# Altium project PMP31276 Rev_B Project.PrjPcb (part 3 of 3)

## Sheet PMP31276 Rev_B LaunchPad Schematic.SchDoc: LaunchPad / Aux supply
size 431 x 279 mm; Date: Not shown in title block; ApprovedBy: Not shown in title block; CheckedBy: Not shown in title block; Author: Not shown in title block; CompanyName: Not shown in title block; DrawnBy: R. Scibilia; Engineer: Not shown in title block; Organization: Not shown in title block; Address1: Not shown in title block; Address2: Not shown in title block; Address3: Not shown in title block; Address4: Not shown in title block; DocumentNumber: 1; Revision: Use project parameter SCH_Rev; SheetNumber: 4; SheetTotal: 5; PageSetup: Record=PageOptions¦CenterHorizontal=True¦CenterVertical=True¦PrintScale=1.00¦XCorrection=1.00¦YCorrection=1.00¦PrintKind=0¦BorderSize=5000000¦LeftOffset=0¦BottomOffset=0¦Orientation=2¦PaperLength=1000¦PaperWidth=1000¦Scale=100¦PaperSource=15¦PrintQuality=600¦MediaType=1¦DitherType=10¦PaperKind=Letter¦PrintScaleMode=1
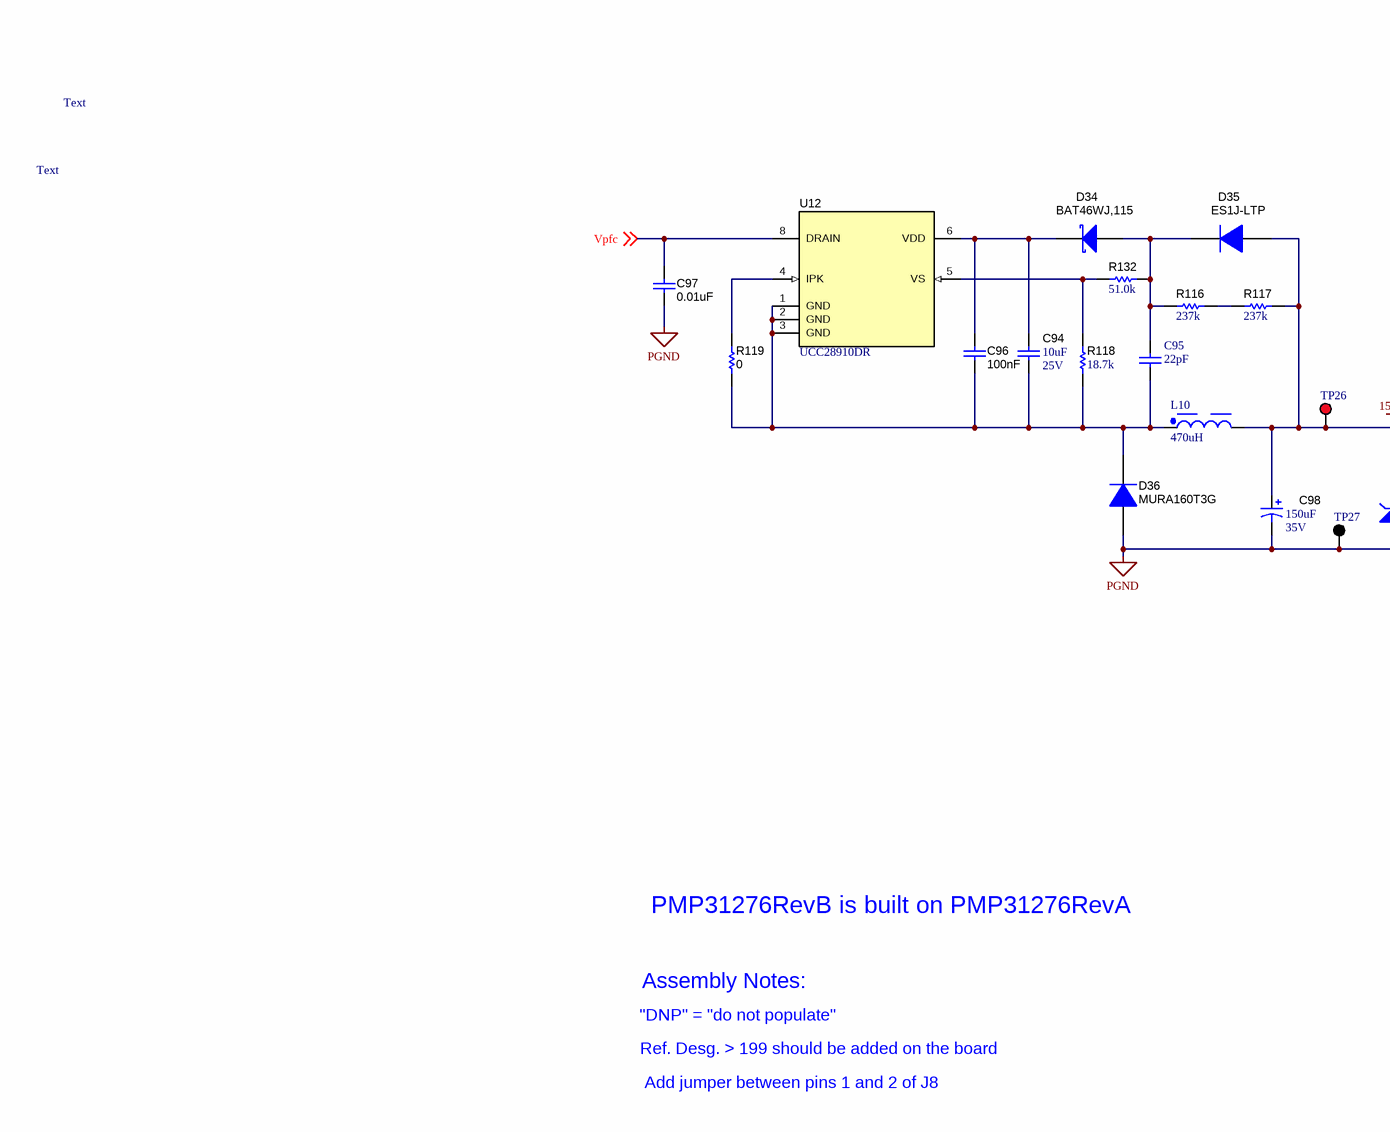
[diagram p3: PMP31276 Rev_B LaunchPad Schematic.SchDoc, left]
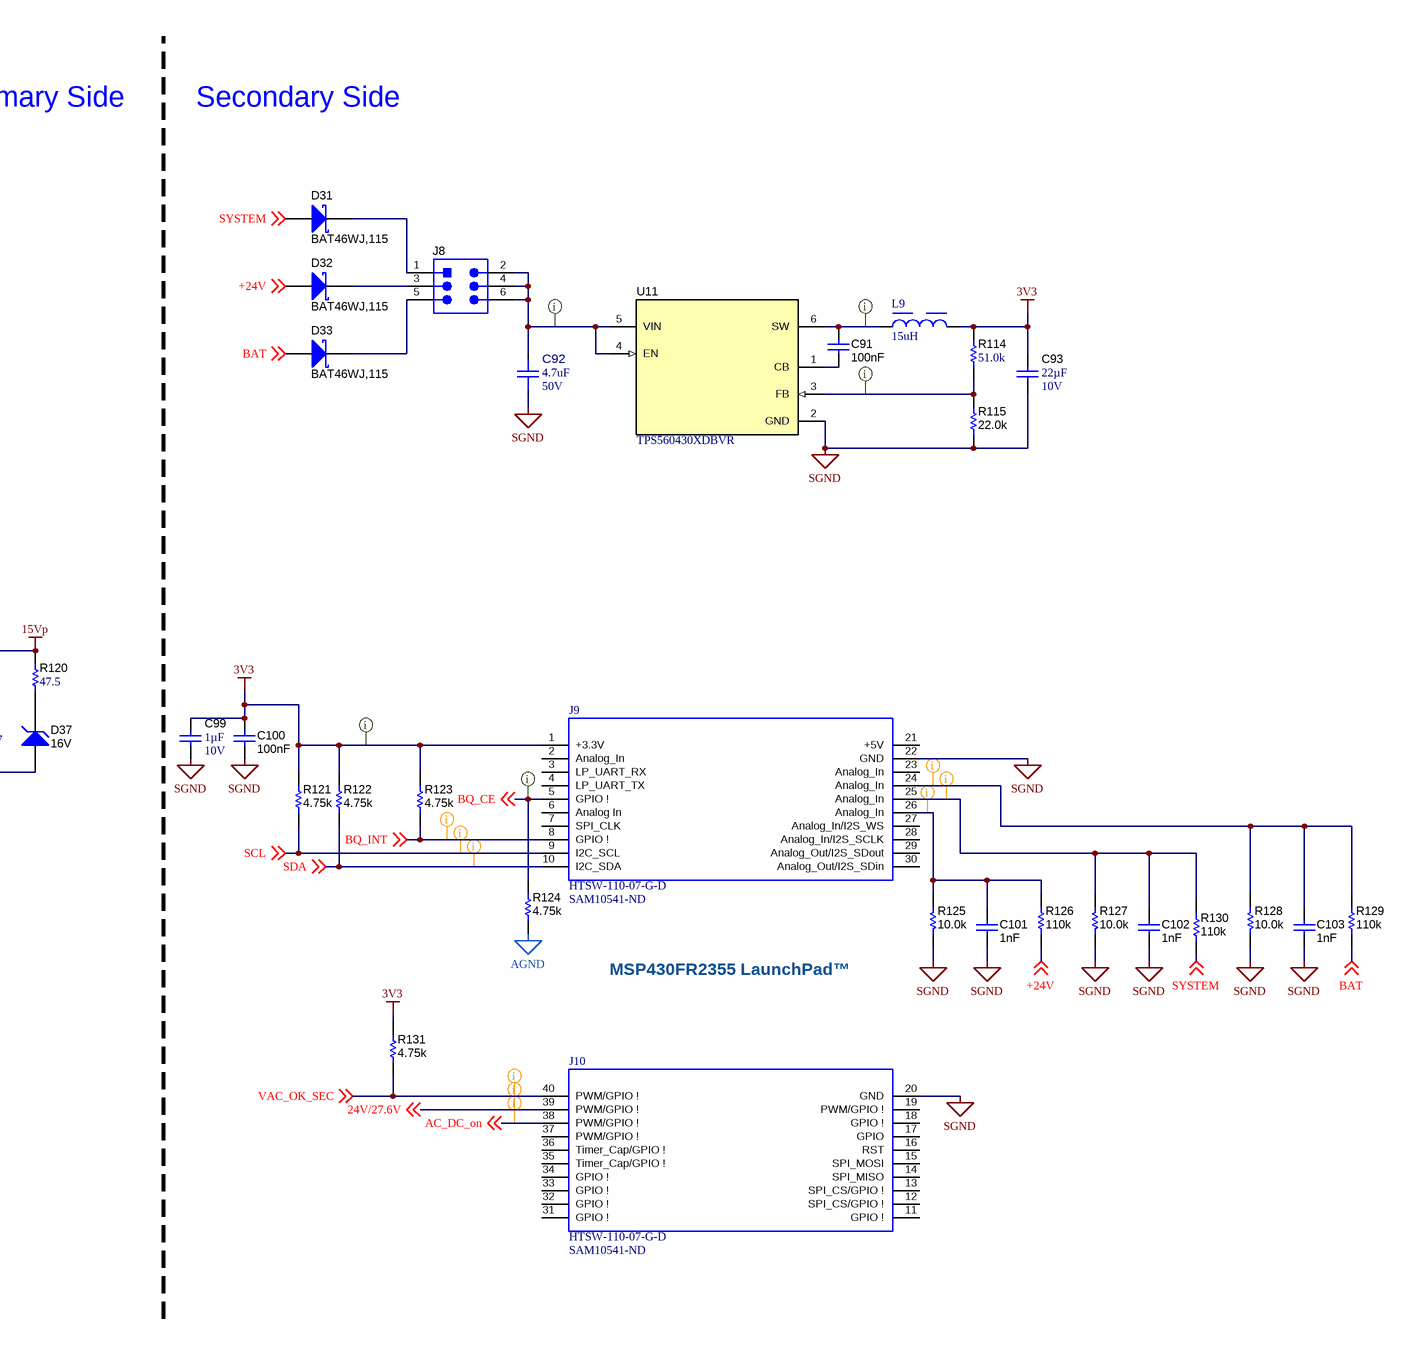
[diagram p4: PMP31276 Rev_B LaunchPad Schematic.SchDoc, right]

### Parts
C91  Cap_F: 100nF  [0603]  (hidden comment: 885012206095)
C92  VDC_V: 50V  ValueDisplayed: 4.7uF  [FP-885012208094_1206-MFG]  (hidden comment: 885012208094)
C93  VDC_V: 10V  ValueDisplayed: 22µF  [0805_150]  (hidden comment: 885012107011)
C94  VDC_V: 25V  ValueDisplayed: 10uF  [1206]  (hidden comment: 885012208069)
C95  value 22pF  [WCAP-CSGP_0603_L1.6W0.8H0.8_Reflow]  (hidden comment: 885012006053)
C96  Cap_F: 100nF  [0603]  (hidden comment: 885012206095)
C97  ValueDisplayed: 0.01uF  [1210]  (hidden comment: 885342208009)
C98  VDC_V: 35V  ValueDisplayed: 150uF  [SM_RADIAL_10BMM]  (hidden comment: UCL1V151MCL6GS)
C99  Cap_F: 1µF  VDC_V: 10V  [0603]  (hidden comment: 885012206026)
C100  Cap_F: 100nF  [0603]  (hidden comment: 885012206095)
C101  Cap_F: 1nF  [0603]  (hidden comment: 885012206083)
C102  Cap_F: 1nF  [0603]  (hidden comment: 885012206083)
C103  Cap_F: 1nF  [0603]  (hidden comment: 885012206083)
D31  BAT46WJ,115  [SOD-323F]
D32  BAT46WJ,115  [SOD-323F]
D33  BAT46WJ,115  [SOD-323F]
D34  BAT46WJ,115  [SOD-323F]
D35  ES1J-LTP  [SMA]
D36  MURA160T3G  [SMA]
D37  value 16V  [SOD-323]  (hidden comment: MM3Z16VST1G)
J8  61300621121  [Wurth_61300621121]  (value not drawn)
J9  HTSW-110-07-G-D  Supplier Part Number 1: SAM10541-ND  [BOOSTERPACK_40PIN_MALE_PART1]
J10  HTSW-110-07-G-D  Supplier Part Number 1: SAM10541-ND  [BOOSTERPACK_40PIN_MALE_PART2]
L9  value 15uH  [WE-MAPI_3015]  (hidden comment: 74438335150)
L10  value 470uH  [WE-PD HV_1060]  (hidden comment: 7687714471)
R114  ValueDisplayed: 51.0k  [0603]  (hidden comment: RC0603FR-0751KL)
R115  ValueDisplayed: 22.0k  [0603]  (hidden comment: RC0603FR-0722KL)
R116  ValueDisplayed: 237k  [1206]  (hidden comment: ERJ-8ENF2373V)
R117  ValueDisplayed: 237k  [1206]  (hidden comment: ERJ-8ENF2373V)
R118  ValueDisplayed: 18.7k  [0603S]  (hidden comment: RC0603FR-0718K7L)
R119  ValueDisplayed: 0  [0603]  (hidden comment: RMCF0603ZT0R00)
R120  ValueDisplayed: 47.5  [0805_HV]  (hidden comment: CRCW080547R5FKEA)
R121  ValueDisplayed: 4.75k  [0603]  (hidden comment: RC0603FR-074K75L)
R122  ValueDisplayed: 4.75k  [0603]  (hidden comment: RC0603FR-074K75L)
R123  ValueDisplayed: 4.75k  [0603]  (hidden comment: RC0603FR-074K75L)
R124  ValueDisplayed: 4.75k  [0603]  (hidden comment: RC0603FR-074K75L)
R125  ValueDisplayed: 10.0k  [0603]  (hidden comment: RC0603FR-0710KL)
R126  ValueDisplayed: 110k  [0603]  (hidden comment: CRCW0603110KFKEA)
R127  ValueDisplayed: 10.0k  [0603]  (hidden comment: RC0603FR-0710KL)
R128  ValueDisplayed: 10.0k  [0603]  (hidden comment: RC0603FR-0710KL)
R129  ValueDisplayed: 110k  [0603]  (hidden comment: CRCW0603110KFKEA)
R130  ValueDisplayed: 110k  [0603]  (hidden comment: CRCW0603110KFKEA)
R131  ValueDisplayed: 4.75k  [0603]  (hidden comment: RC0603FR-074K75L)
R132  ValueDisplayed: 51.0k  [0603]  (hidden comment: RC0603FR-0751KL)
TP26  5000  [Keystone5000]  (value not drawn)
TP27  5001  [Keystone5001]  (value not drawn)
U11  TPS560430XDBVR  [DBV0006A_N]
U12  UCC28910DR  [D0007A_N]

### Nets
3V3: C93.1 C99.1 C100.2 J9.1(+3.3V) L9.2 R114.2 R121.2 R122.2 R123.2 R131.2
15Vp: C98.1(+) D35.2(A) L10.2 R117.2 R120.2 TP26.1
AGND: R124.1
PGND: C97.2 C98.2(-) D36.2(A) D37.2(A) TP27.1
SGND: C92.1 C93.2 C99.2 C100.1 C101.2 C102.2 C103.2 J9.22(GND) J10.20(GND) R115.1 R125.2 R127.2 R128.2 U11.2(GND)
24V/27.6V: J10.39(PWM/GPIO_!) ; off-sheet 24V/27.6V
+24V: D32.2(A) R126.1 ; off-sheet +24V
AC_DC_on: J10.38(PWM/GPIO_!) ; off-sheet AC_DC_on
BAT: D33.2(A) R129.2 ; off-sheet BAT
BQ_CE: J9.5(GPIO_!) R124.2 ; off-sheet BQ_CE
BQ_INT: J9.8(GPIO_!) R123.1 ; off-sheet BQ_INT
SCL: J9.9(I2C_SCL) R121.1 ; off-sheet SCL
SDA: J9.10(I2C_SDA) R122.1 ; off-sheet SDA
SYSTEM: D31.2(A) R130.2 ; off-sheet SYSTEM
VAC_OK_SEC: J10.40(PWM/GPIO_!) R131.1 ; off-sheet VAC_OK_SEC
Vpfc: C97.1 U12.8(DRAIN) ; off-sheet Vpfc
NetC91_1: C91.1 U11.1(CB)
NetC91_2: C91.2 L9.1 U11.6(SW)
NetC92_2: C92.2 J8.2 J8.4 J8.6 U11.4(EN) U11.5(VIN)
NetC94_1: C94.1 C96.2 D34.1(K) U12.6(VDD)
NetC94_2: C94.2 C95.1 C96.1 D36.1(K) L10.1 R118.1 R119.1 U12.1(GND) U12.2(GND) U12.3(GND)
NetC95_2: C95.2 D34.2(A) D35.1(K) R116.1 R132.1
NetC101_1: C101.1 J9.26(Analog_In) R125.1 R126.2
NetC102_1: C102.1 J9.25(Analog_In) R127.1 R130.1
NetC103_1: C103.1 J9.24(Analog_In) R128.1 R129.1
NetD31_1: D31.1(K) J8.1
NetD32_1: D32.1(K) J8.3
NetD33_1: D33.1(K) J8.5
NetD37_1: D37.1(K) R120.1
NetR114_1: R114.1 R115.2 U11.3(FB)
NetR116_2: R116.2 R117.1
NetR118_2: R118.2 R132.2 U12.5(VS)
NetR119_2: R119.2 U12.4(IPK)

Not connected (* = marked no-connect by the designer): J9 2(Analog_In) 3(LP_UART_RX) 4(LP_UART_TX) 6(Analog_In) 7(SPI_CLK) 21(+5V) 23(Analog_In) 27(Analog_In/I2S_WS) 28(Analog_In/I2S_SCLK) 29(Analog_Out/I2S_SDout) 30(Analog_Out/I2S_SDin); J10 11(GPIO_!) 12(SPI_CS/GPIO_!) 13(SPI_CS/GPIO_!) 14(SPI_MISO) 15(SPI_MOSI) 16(RST) 17(GPIO) 18(GPIO_!) 19(PWM/GPIO_!) 31(GPIO_!) 32(GPIO_!) 33(GPIO_!) 34(GPIO_!) 35(Timer_Cap/GPIO_!) 36(Timer_Cap/GPIO_!) 37(PWM/GPIO_!)

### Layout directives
rule Clearance Constraint [Clearance = 10mil]: 3V3, BQ_CE, NetC91_2, NetC92_2, NetR114_1
rule Clearance Constraint [Clearance = 9mil]: 24V/27.6V, AC_DC_on, BQ_INT, NetC101_1, NetC102_1, NetC103_1, SCL, SDA, VAC_OK_SEC

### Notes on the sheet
- Primary Side
- Secondary Side
- Text
- MSP430FR2355 LaunchPad™
- PMP31276RevB is built on PMP31276RevA
- Assembly Notes:
- "DNP" = "do not populate"
- Add jumper between pins 1 and 2 of J8
- Ref. Desg. > 199 should be added on the board

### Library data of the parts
C91 C96 C100 = CMP-0006837-3: CAP, CERM, 0.1 uF, 50 V, +/- 10%, X7R, 0603; Manufacturer: Wurth Elektronik; TaMin_C: -55°C; Polarized: N; SizeAreaWB_mm2: 4.68; Value1: Unknown; U/M: EA; Value: 0.1uF; TaMax_C: 125°C; SizeZ_mm: 1; SizeX_mm: 1.6; SizeY_mm: 0.8; Value2: 50V; SizeArea_mm2: 1.28; AEC Category: Q200
C92 = CMP-0088282-2: 4.7µF ±10% 50V Ceramic Capacitor X7R 1206 (3216 Metric); Manufacturer: Wurth Electronics; TempCo: 15%; Symbol Name: SYM-885012208094; SizeZ_mm: 1.9mm; AEC Qualified: No
C93 = CMP-0078153-1: CAP, CERM, 22 µF, 10 V,+/- 20%, X5R, 0805; Manufacturer: Wurth Elektronik; TaMin_C: -55°C; Polarized: N; SizeAreaWB_mm2: 6.75; U/M: EA; Value: 22uF; TaMax_C: 85°C; SizeZ_mm: 1.5; SizeX_mm: 2; SizeY_mm: 1.25; Cap_Case: 0805; SizeArea_mm2: 2.5; AEC Category: Q200
C94 = CMP-0008574-2: CAP, CERM, 10 uF, 25 V, +/- 10%, X7R, 1206; Manufacturer: Wurth Elektronik; TaMin_C: -55°C; Polarized: N; SizeAreaWB_mm2: 10.92; Value1: Unknown; U/M: EA; Value: 10uF; TaMax_C: 125°C; SizeZ_mm: 1.35; SizeX_mm: 3.2; SizeY_mm: 1.6; SizeArea_mm2: 5.12; Cap_F: 10µF; AEC Category: Q200
C95 = CMP-0111392-1: WCAP-CSGP Multilayer Ceramic Chip Capacitor, General Purpose, size 0603, NP0, 22pF, 50VDC; Manufacturer: Wurth Elektronik; Capacitance Tolerance: +/-5%; Case/Size Code: 0603; Q Factor: 840; Insulation Resistance: 10GOhm; Rated Voltage (DC): 50V; Technical Reference: NP00603220J050DFCT10000
C97 = CMP-0009273-2: CAP, CERM, 0.01 uF, 500 V, +/- 10%, X7R, 1206; Manufacturer: Wuerth; TaMin_C: -55°C; Polarized: N; SizeAreaWB_mm2: 14.7; Value1: Unknown; U/M: EA; Value: 0.01uF; TaMax_C: 125°C; SizeZ_mm: 1.35; SizeX_mm: 3.2; SizeY_mm: 2.5; Cap_Case: 1206; Value2: 500V; SizeArea_mm2: 8; Cap_F: 10nF; AEC Category: Q200
C98 = CMP-0011092-1: CAP, AL, 150 uF, 35 V, +/- 20%, 0.1 ohm, SMD; Manufacturer: Nichicon; TaMin_C: -55°C; ESR_ohm: 100m; Polarized: Y; SizeAreaWB_mm2: 159.9; Value1: 0.1 ohm; U/M: EA; Value: 150uF; TaMax_C: 105°C; SizeZ_mm: 10.2; SizeX_mm: 11; SizeY_mm: 10.3; Cap_Case: 10x10; SizeArea_mm2: 113.3; CompType: Capacitor; Cap_F: 150µF; IRMS_A: 850mA; AEC Category: Q200
C99 = CMP-0064932-4: CAP, CERM, 1 uF, 10 V,+/- 10%, X7R, 0603; Manufacturer: Wurth Elektronik; TaMin_C: -55°C; Polarized: N; SizeAreaWB_mm2: 4.68; Value1: Unknown; U/M: EA; Value: 1uF; TaMax_C: 125°C; SizeZ_mm: 1; SizeX_mm: 1.6; SizeY_mm: 0.8; SizeArea_mm2: 1.28; AEC Category: Q200
C101-C103 = CMP-0064933-4: CAP, CERM, 1000 pF, 50 V,+/- 10%, X7R, 0603; Manufacturer: Wurth Elektronik; TaMin_C: -55°C; Polarized: N; SizeAreaWB_mm2: 4.68; Value1: Unknown; U/M: EA; Value: 1000pF; TaMax_C: 125°C; SizeZ_mm: 1; SizeX_mm: 1.6; SizeY_mm: 0.8; Value2: 50V; SizeArea_mm2: 1.28; AEC Category: Q200
D31-D34 = CMP-0076946-2: Diode, Schottky, 100 V, 0.25 A, SOD-323F; Manufacturer: Nexperia; SizeAreaWB_mm2: 7.875; Value2: 0.85V; SizeX_mm: 2.5; Green_REACh: Incomplete; SizeArea_mm2: 3.125; Vf_V: 850mV; Green_Lifecycle: Not Set; Vr_V: 100V; TJmax_C: 150°C; Value1: 0.25A; Io_A: 250mA; SizeZ_mm: 0.8; Value: 100V; AEC Category: Q101; SizeY_mm: 1.25
D35 = CMP-0077053-2: Diode, Superfast Rectifier, 600 V, 1 A, SMA; Manufacturer: Micro Commercial Components; AEC Category: Q101; SizeZ_mm: 2.87; Green_REACh: Incomplete; Value: 600V; SizeAreaWB_mm2: 37.3428; SizeY_mm: 2.92; TJmax_C: 175°C; SizeX_mm: 5.59; SizeArea_mm2: 16.3228; Value2: 1.7V; Green_Lifecycle: Not Set; Io_A: 1A
D36 = CMP-0029033-2: Diode, Ultrafast, 600 V, 1 A, AEC-Q101, SMA; Manufacturer: ON Semiconductor; AEC Category: Q101; SizeX_mm: 5.59; Io_A: 1A; Green_Lifecycle: Active; Value2: 1.05V; SizeArea_mm2: 16.3228; SizeZ_mm: 2.87; TJmax_C: 175°C; Value: 600V; AEC Qualified: Y; SizeAreaWB_mm2: 37.3428; SizeY_mm: 2.92; Green_REACh: Passed
D37 = CMP-0085764-1: Diode, Zener, 16 V, 300 mW, SOD-323; Manufacturer: ON Semiconductor; Power_W: 300mW; SizeZ_mm: 1; SizeArea_mm2: 3.645; SizeX_mm: 2.7; SizeY_mm: 1.35; RJA_CperW: 416; Value1: 0.3W; SizeAreaWB_mm2: 8.695; AEC Qualified: N; AEC Category: Q101
J8 = CMP-0054802-2: Header, 2.54mm, 3x2, Gold, TH; Manufacturer: Wurth Elektronik; Green_Lifecycle: Active; Shrouded: N; Gender: Male; Green_REACh: Passed; Row_Count: 2; RowSpacing_mm: 2.54
J9 = LaunchPadPart1: HTSW - Samtec 2.54mm High-Temp Terminal Strip / Header; Number of Positions: 20; Gender: Male; Pitch: 0.1inch
J10 = launchPad Part2: HTSW - Samtec 2.54mm High-Temp Terminal Strip / Header; Number of Positions: 20; Gender: Male; Pitch: 0.1inch
L9 = CMP-0099107-1: WE-MAPI SMT Power Inductor, size 3015, 15uH, 0.65A, 830mOhm; Manufacturer: Wurth Elektronik; Case/Size Code: 3015; DC Resistance: 720mOhm; Saturation Current: 1.71A; Self Resonant Frequency: 14MHz
L10 = CMP-0101506-1: WE-PD HV SMT High Voltage Power Inductor, size 1060, 470uH, 0.6A, 1.45Ohm; Manufacturer: Wurth Elektronik; Case/Size Code: 1060; DC Resistance: 1.25Ohm; Operating Voltage (DC): 400V; Saturation Current: 0.8A; Self Resonant Frequency: 2.7MHz
R114 R132 = CMP-0023167-5: RES, 51.0 k, 1%, 0.1 W, 0603; Manufacturer: Yageo; Power_W: 100mW; TempCo: 100 ppm/C; Value_Code: 51k0; Value: 51.0k; Res_ohm: 51k; SizeX_mm: 1.6; SizeY_mm: 0.8; SizeZ_mm: 1; Value2: 0.1W; SizeArea_mm2: 1.28; AEC Qualified: N; VDC_V: 75V; AEC Category: Q200; SizeAreaWB_mm2: 4.68
R115 = CMP-0022925-5: RES, 22.0 k, 1%, 0.1 W, 0603; Manufacturer: Yageo; Power_W: 100mW; TempCo: 100 ppm/C; Value_Code: 22k0; Value: 22.0k; Res_ohm: 22k; SizeX_mm: 1.6; SizeY_mm: 0.8; SizeZ_mm: 1; Value2: 0.1W; SizeArea_mm2: 1.28; AEC Qualified: N; VDC_V: 75V; AEC Category: Q200; SizeAreaWB_mm2: 4.68
R116 R117 = CMP-0017472-3: RES, 237 k, 1%, 0.25 W, AEC-Q200 Grade 0, 1206; Manufacturer: Panasonic; Power_W: 250mW; TempCo: 100 ppm/C; Value: 237k; EIA_Code: E96; SizeX_mm: 3.2; SizeY_mm: 1.6; SizeZ_mm: 1.35; Value2: 0.25W; SizeArea_mm2: 5.12; AEC Qualified: Y; VDC_V: 200V; AEC Category: Q200; AEC Grade: 0; SizeAreaWB_mm2: 10.92
R118 = CMP-0022851-5: RES, 18.7 k, 1%, 0.1 W, 0603; Manufacturer: Yageo; Power_W: 100mW; TempCo: 100 ppm/C; Value_Code: 18k7; Value: 18.7k; EIA_Code: E96; SizeX_mm: 1.6; SizeY_mm: 0.8; SizeZ_mm: 1; Value2: 0.1W; SizeArea_mm2: 1.28; AEC Qualified: N; VDC_V: 75V; AEC Category: Q200; SizeAreaWB_mm2: 4.68
R119 = CMP-0023343-3: RES, 0, 1%, 0.1 W, AEC-Q200 Grade 0, 0603; Manufacturer: Stackpole Electronics Inc; Power_W: 100mW; TempCo: ppm/C; U/M: EA; Value: 0; SizeX_mm: 1.6; SizeY_mm: 0.8; SizeZ_mm: 1; Value2: 0.1W; SizeArea_mm2: 1.28; AEC Qualified: Y; AEC Category: Q200
R120 = CMP-0021276-3: RES, 47.5, 1%, 0.125 W, AEC-Q200 Grade 0, 0805; Manufacturer: Vishay-Dale; Power_W: 125mW; TempCo: 100 ppm/C; Value_Code: 47R5; Value: 47.5; EIA_Code: E96; SizeX_mm: 2; SizeY_mm: 1.25; SizeZ_mm: 1.45; Value2: 0.125W; SizeArea_mm2: 2.5; AEC Qualified: Y; VDC_V: 150V; AEC Category: Q200; AEC Grade: 0
R121-R124 R131 = CMP-0023152-5: RES, 4.75 k, 1%, 0.1 W, 0603; Manufacturer: Yageo; Power_W: 100mW; TempCo: 100 ppm/C; Value_Code: 4k75; Value: 4.75k; EIA_Code: E96; SizeX_mm: 1.6; SizeY_mm: 0.8; SizeZ_mm: 1; Value2: 0.1W; SizeArea_mm2: 1.28; AEC Qualified: N; VDC_V: 75V; AEC Category: Q200; SizeAreaWB_mm2: 4.68
R125 R127 R128 = CMP-0022746-5: RES, 10.0 k, 1%, 0.1 W, 0603; Manufacturer: Yageo; Power_W: 100mW; TempCo: 100 ppm/C; Value_Code: 10k0; Value: 10.0k; EIA_Code: E96; Res_ohm: 10k; SizeX_mm: 1.6; SizeY_mm: 0.8; SizeZ_mm: 1; Value2: 0.1W; SizeArea_mm2: 1.28; AEC Qualified: N; VDC_V: 75V; AEC Category: Q200; SizeAreaWB_mm2: 4.68
R126 R129 R130 = CMP-0022008-4: RES, 110 k, 1%, 0.1 W, AEC-Q200 Grade 0, 0603; Manufacturer: Vishay-Dale; Power_W: 100mW; TempCo: 100 ppm/C; Value: 110k; EIA_Code: E96; SizeX_mm: 1.6; SizeY_mm: 0.8; SizeZ_mm: 1; Value2: 0.1W; SizeArea_mm2: 1.28; AEC Qualified: Y; VDC_V: 75V; AEC Category: Q200; AEC Grade: 0
TP26 = CMP-0055137-2: Test Point, Miniature, Red, TH; Manufacturer: Keystone Electronics; Green_REACh: Passed; Green_Lifecycle: Active; ContactFinish: Silver; CNHeader: FALSE; CT: TRUE
TP27 = CMP-0055138-2: Test Point, Miniature, Black, TH; Manufacturer: Keystone Electronics; ContactFinish: Silver; CNHeader: FALSE; Green_Lifecycle: Active; Green_REACh: Passed; CT: TRUE
U11 = CMP-0065097-3: 4V to 36 V 0.6 A Synchronous Step-Down Converter, DBV0006A (SOT-23-6); Manufacturer: Texas Instruments; Alternate PartNumber: TPS560430XDBVT; SizeX_mm: 2.8; SizeY_mm: 2.9; CompType: IC; SizeZ_mm: 1.45; SizeArea_mm2: 8.12; SizeAreaWB_mm2: 14.82; U/M: EA
U12 = CMP-0067241-2: 700V Flyback Switcher with Constant-Voltage Constant-Current and Primary-side Control, D0007A (SOIC-7); Alternate Manufacturer: Texas Instruments; SizeAreaWB_mm2: 55.2; U/M: EA; SizeZ_mm: 1.75; SizeX_mm: 6.0; SizeY_mm: 4.9; SizeArea_mm2: 29.4; CompType: IC; AEC Category: Q200; AEC Qualified: N

## Sheet PMP31276 Rev_B Hardware.SchDoc: Hardware
size 431 x 279 mm; Date: Not shown in title block; ApprovedBy: Not shown in title block; CheckedBy: Not shown in title block; Author: Not shown in title block; CompanyName: Not shown in title block; DrawnBy: R. Scibilia; Engineer: R. Scibilia; Organization: Not shown in title block; Address1: Not shown in title block; Address2: Not shown in title block; Address3: Not shown in title block; Address4: Not shown in title block; DocumentNumber: 1; Revision: Use project parameter SCH_Rev; SheetNumber: 5; SheetTotal: 5; PageSetup: Record=PageOptions¦CenterHorizontal=True¦CenterVertical=True¦PrintScale=1.00¦XCorrection=1.00¦YCorrection=1.00¦PrintKind=0¦BorderSize=5000000¦LeftOffset=0¦BottomOffset=0¦Orientation=2¦PaperLength=1000¦PaperWidth=1000¦Scale=100¦PaperSource=15¦PrintQuality=600¦MediaType=1¦DitherType=10¦PaperKind=Letter¦PrintScaleMode=1
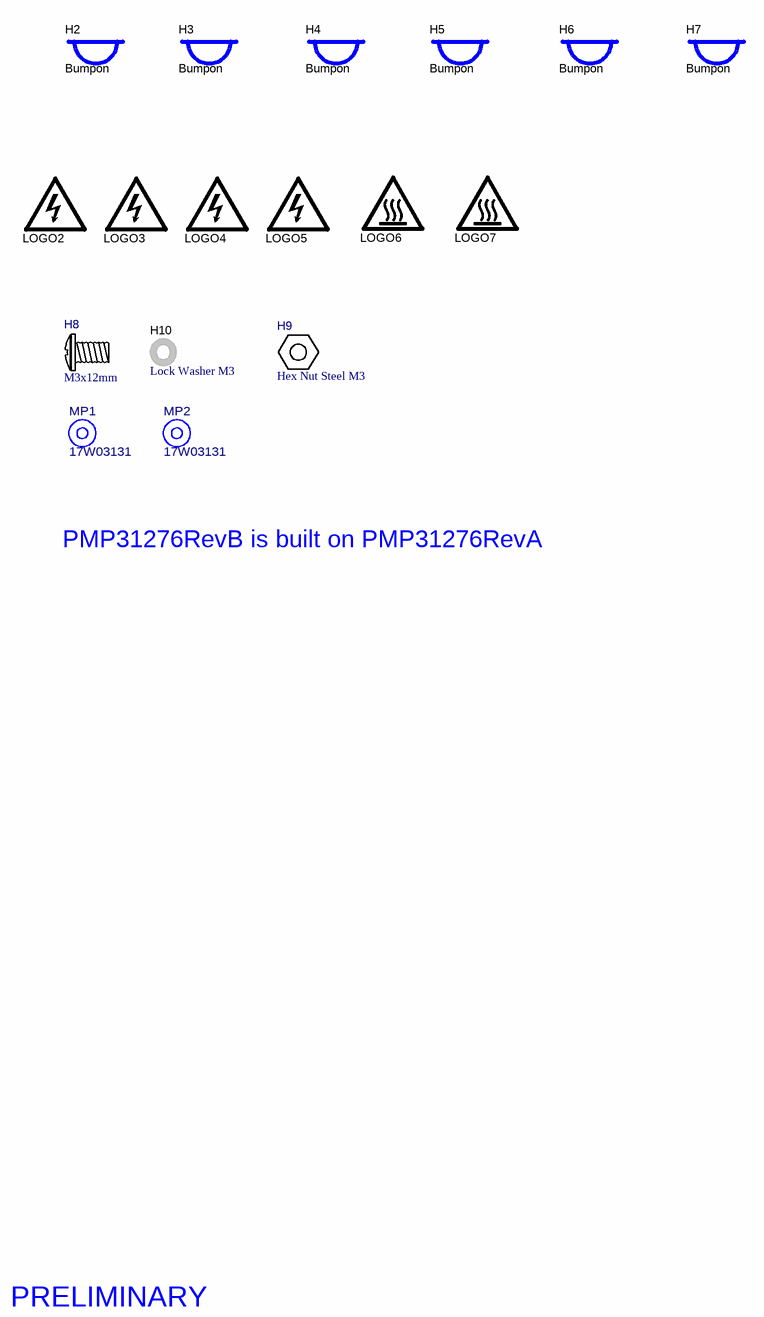
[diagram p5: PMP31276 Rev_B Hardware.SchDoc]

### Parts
H2  Bumpon  [Bumpon_SJ5003Transparent]
H3  Bumpon  [Bumpon_SJ5003Transparent]
H4  Bumpon  [Bumpon_SJ5003Transparent]
H5  Bumpon  [Bumpon_SJ5003Transparent]
H6  Bumpon  [Bumpon_SJ5003Transparent]
H7  Bumpon  [Bumpon_SJ5003Transparent]
H8  value M3x12mm  (hidden comment: RM3X12MM 2701)  (mechanical)
H9  value Hex Nut Steel M3  (hidden comment: 4708)  (mechanical)
H10  value Lock Washer M3  (hidden comment: MLWZ 003)  (mechanical)
LOGO2  DANGER HIGH VOLTAGE  [IEC_HighVoltage_Small]  (value not drawn)  (no BOM)
LOGO3  DANGER HIGH VOLTAGE  [IEC_HighVoltage_Small]  (value not drawn)  (no BOM)
LOGO4  DANGER HIGH VOLTAGE  [IEC_HighVoltage_Small]  (value not drawn)  (no BOM)
LOGO5  DANGER HIGH VOLTAGE  [IEC_HighVoltage_Small]  (value not drawn)  (no BOM)
LOGO6  CAUTION HOT SURFACE  [IEC_HotSurface_Small]  (value not drawn)  (no BOM)
LOGO7  CAUTION HOT SURFACE  [IEC_HotSurface_Small]  (value not drawn)  (no BOM)
MP1  17W03131  [FP-17W03131_WASHER-MFG]
MP2  17W03131  [FP-17W03131_WASHER-MFG]

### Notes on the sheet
- PMP31276RevB is built on PMP31276RevA
- PRELIMINARY

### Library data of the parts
H2-H7 = CMP-0003620-1: Bumpon, Hemisphere, 0.44 X 0.20, Clear; Manufacturer: 3M; PartNumber: SJ-5303 (CLEAR)
H8 = CMP-0003849-1: SCREW, M3X4MM, FH, SS, MACHIN; Manufacturer: APM Hexseal; Key: 10109; CompType: Hardware
H9 = CMP-0003742-1: HEX NUT 0.217" STEEL M3; Manufacturer: Keystone; CompType: Standoff
H10 = CMP-0003664-1: Lock Washer, split, M3, Steel; Manufacturer: B&F Fastener Supply; Key: 7235-2
LOGO2-LOGO5 = CMP-0074835-1: IEC 61010-1 High Voltage Warning; SymbolCreator: a0412235
LOGO6 LOGO7 = CMP-0074837-1: IEC 61010-1 Hot Surface Warning; SymbolCreator: a0412235
MP1 MP2 = CMP-0126820-1: Flat Washer 0.020" (0.51mm) Thick Nylon; Manufacturer: Essentra Components; AEC Qualified: No; SizeZ_mm: 0.65mm

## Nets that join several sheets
3V3: PMP31276 Rev_B PFC Schematic (R39.2), PMP31276 Rev_B Charger Schematic (D26.2 D27.2 D28.2), PMP31276 Rev_B LaunchPad Schematic (10 pins)
15Vp: PMP31276 Rev_B PFC Schematic (D9.1 Q4.3 R10.2 R12.2), PMP31276 Rev_B LaunchPad Schematic (6 pins)
15Vp-sw: PMP31276 Rev_B PFC Schematic (C19.1 Q5.3 TP17.1 U3.12), PMP31276 Rev_B LLC Schematic (5 pins)
AGND: PMP31276 Rev_B Charger Schematic (13 pins), PMP31276 Rev_B LaunchPad Schematic (R124.1)
PGND: PMP31276 Rev_B PFC Schematic (27 pins), PMP31276 Rev_B LLC Schematic (12 pins), PMP31276 Rev_B LaunchPad Schematic (5 pins)
SGND: PMP31276 Rev_B PFC Schematic (U4.3), PMP31276 Rev_B LLC Schematic (35 pins), PMP31276 Rev_B Charger Schematic (35 pins), PMP31276 Rev_B LaunchPad Schematic (14 pins)
24V/27.6V: PMP31276 Rev_B LLC Schematic (R84.1), PMP31276 Rev_B LaunchPad Schematic (J10.39)
+24V: PMP31276 Rev_B LLC Schematic (6 pins), PMP31276 Rev_B Charger Schematic (15 pins), PMP31276 Rev_B LaunchPad Schematic (D32.2 R126.1)
AC_DC_on: PMP31276 Rev_B PFC Schematic (U5.2), PMP31276 Rev_B LaunchPad Schematic (J10.38)
BAT: PMP31276 Rev_B Charger Schematic (9 pins), PMP31276 Rev_B LaunchPad Schematic (D33.2 R129.2)
BQ_CE: PMP31276 Rev_B Charger Schematic (U10.7), PMP31276 Rev_B LaunchPad Schematic (J9.5 R124.2)
BQ_INT: PMP31276 Rev_B Charger Schematic (U10.3), PMP31276 Rev_B LaunchPad Schematic (J9.8 R123.1)
SCL: PMP31276 Rev_B Charger Schematic (J5.2 U10.1), PMP31276 Rev_B LaunchPad Schematic (J9.9 R121.1)
SDA: PMP31276 Rev_B Charger Schematic (J5.3 U10.2), PMP31276 Rev_B LaunchPad Schematic (J9.10 R122.1)
SYSTEM: PMP31276 Rev_B Charger Schematic (19 pins), PMP31276 Rev_B LaunchPad Schematic (D31.2 R130.2)
VAC_OK_SEC: PMP31276 Rev_B PFC Schematic (U4.4), PMP31276 Rev_B LaunchPad Schematic (J10.40 R131.1)
Vpfc: PMP31276 Rev_B PFC Schematic (11 pins), PMP31276 Rev_B LLC Schematic (C32.1 C33.2 Q9.4 R66.2), PMP31276 Rev_B LaunchPad Schematic (C97.1 U12.8)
